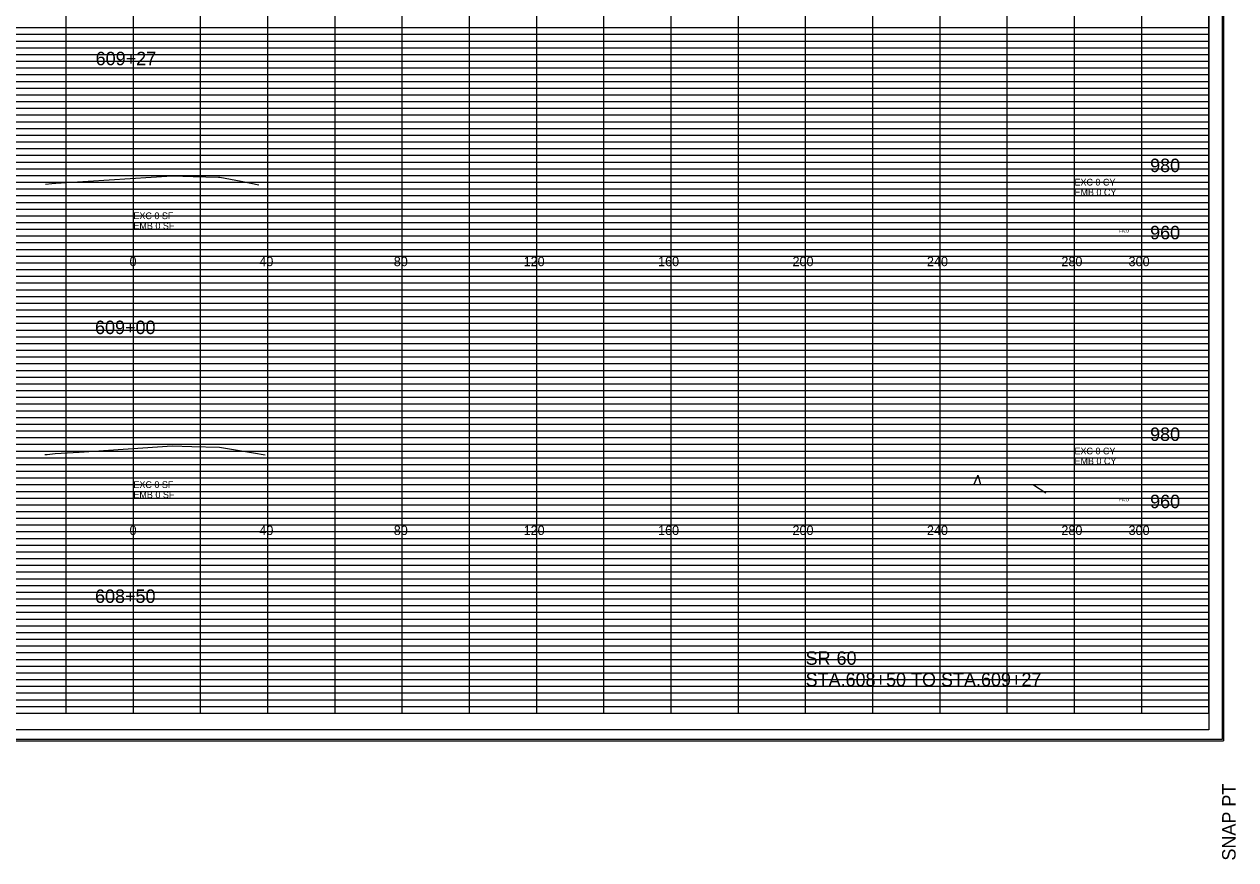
# Model space of a CAD drawing. Extents: x 2313580 to 2322968, y 282099 to 303247.
# Drawn here: x 2321916 to 2322276.5, y 287544 to 287792.7 of the extents above; entities that cross this region are included whole.
import ezdxf

# ---------------------------------------------------------------- set-up
doc = ezdxf.new("R2010")
doc.units = 0
for name, color, linetype in [('DESIGN - EARTHWORK - Excavation Limit Lines', 7, 'Continuous'), ('DESIGN - SHEET - Corner Text', 7, 'Continuous'), ('DESIGN - SHEET - Light Grid', 7, 'Continuous'), ('DESIGN - SHEET - Linework', 7, 'Continuous'), ('DESIGN - SHEET - Plot Shape', 7, 'Continuous'), ('DESIGN - TYPICAL - Text', 7, 'Continuous'), ('Prop_ CL text', 7, 'Continuous'), ('SURVEY - GROUND - Top of Ground', 7, 'Continuous')]:
    doc.layers.add(name, color=color, linetype=linetype)

msp = doc.modelspace()

# ---------------------------------------------------------------- linework, layer by layer
at = {"layer": 'DESIGN - SHEET - Light Grid'}
for p, q in [((2321788.48, 287791.67), (2321948.48, 287791.67)), ((2321788.48, 287789.67), (2321948.48, 287789.67)), ((2321948.48, 287791.67), (2322108.48, 287791.67)), ((2321948.48, 287789.67), (2322108.48, 287789.67)), ((2322108.48, 287791.67), (2322268.48, 287791.67)), ((2322108.48, 287789.67), (2322268.48, 287789.67)), ((2321788.48, 287785.67), (2321948.48, 287785.67)), ((2321948.48, 287785.67), (2322108.48, 287785.67)), ((2322108.48, 287785.67), (2322268.48, 287785.67)), ((2321788.48, 287783.67), (2321948.48, 287783.67)), ((2321788.48, 287781.67), (2321948.48, 287781.67)), ((2321948.48, 287783.67), (2322108.48, 287783.67)), ((2321948.48, 287781.67), (2322108.48, 287781.67)), ((2322108.48, 287783.67), (2322268.48, 287783.67)), ((2322108.48, 287781.67), (2322268.48, 287781.67)), ((2321788.48, 287779.67), (2321948.48, 287779.67)), ((2321788.48, 287777.67), (2321948.48, 287777.67)), ((2321948.48, 287779.67), (2322108.48, 287779.67)), ((2321948.48, 287777.67), (2322108.48, 287777.67)), ((2322108.48, 287779.67), (2322268.48, 287779.67)), ((2322108.48, 287777.67), (2322268.48, 287777.67)), ((2321788.48, 287775.67), (2321948.48, 287775.67)), ((2321948.48, 287775.67), (2322108.48, 287775.67)), ((2322108.48, 287775.67), (2322268.48, 287775.67)), ((2321788.48, 287773.67), (2321948.48, 287773.67)), ((2321788.48, 287771.67), (2321948.48, 287771.67)), ((2321948.48, 287773.67), (2322108.48, 287773.67)), ((2321948.48, 287771.67), (2322108.48, 287771.67)), ((2322108.48, 287773.67), (2322268.48, 287773.67)), ((2322108.48, 287771.67), (2322268.48, 287771.67)), ((2321788.48, 287769.67), (2321948.48, 287769.67)), ((2321948.48, 287769.67), (2322108.48, 287769.67)), ((2322108.48, 287769.67), (2322268.48, 287769.67)), ((2321788.48, 287765.67), (2321948.48, 287765.67)), ((2321788.48, 287763.67), (2321948.48, 287763.67)), ((2321948.48, 287765.67), (2322108.48, 287765.67)), ((2321948.48, 287763.67), (2322108.48, 287763.67)), ((2322108.48, 287765.67), (2322268.48, 287765.67)), ((2322108.48, 287763.67), (2322268.48, 287763.67)), ((2321788.48, 287761.67), (2321948.48, 287761.67)), ((2321788.48, 287759.67), (2321948.48, 287759.67)), ((2321948.48, 287761.67), (2322108.48, 287761.67)), ((2321948.48, 287759.67), (2322108.48, 287759.67)), ((2322108.48, 287761.67), (2322268.48, 287761.67)), ((2322108.48, 287759.67), (2322268.48, 287759.67)), ((2321788.48, 287757.67), (2321948.48, 287757.67)), ((2321948.48, 287757.67), (2322108.48, 287757.67)), ((2322108.48, 287757.67), (2322268.48, 287757.67)), ((2321788.48, 287755.67), (2321948.48, 287755.67)), ((2321788.48, 287753.67), (2321948.48, 287753.67)), ((2321948.48, 287755.67), (2322108.48, 287755.67)), ((2321948.48, 287753.67), (2322108.48, 287753.67)), ((2322108.48, 287755.67), (2322268.48, 287755.67)), ((2322108.48, 287753.67), (2322268.48, 287753.67)), ((2321788.48, 287751.67), (2321948.48, 287751.67)), ((2321788.48, 287749.67), (2321948.48, 287749.67)), ((2321948.48, 287751.67), (2322108.48, 287751.67)), ((2321948.48, 287749.67), (2322108.48, 287749.67)), ((2322108.48, 287751.67), (2322268.48, 287751.67)), ((2322108.48, 287749.67), (2322268.48, 287749.67)), ((2321788.48, 287745.67), (2321948.48, 287745.67)), ((2321948.48, 287745.67), (2322108.48, 287745.67)), ((2322108.48, 287745.67), (2322268.48, 287745.67)), ((2321788.48, 287743.67), (2321948.48, 287743.67)), ((2321788.48, 287741.67), (2321948.48, 287741.67)), ((2321948.48, 287743.67), (2322108.48, 287743.67)), ((2321948.48, 287741.67), (2322108.48, 287741.67)), ((2322108.48, 287743.67), (2322268.48, 287743.67)), ((2322108.48, 287741.67), (2322268.48, 287741.67)), ((2321788.48, 287739.67), (2321948.48, 287739.67)), ((2321948.48, 287739.67), (2322108.48, 287739.67)), ((2322108.48, 287739.67), (2322268.48, 287739.67)), ((2321788.48, 287737.67), (2321948.48, 287737.67)), ((2321788.48, 287735.67), (2321948.48, 287735.67)), ((2321948.48, 287737.67), (2322108.48, 287737.67)), ((2321948.48, 287735.67), (2322108.48, 287735.67)), ((2322108.48, 287737.67), (2322268.48, 287737.67)), ((2322108.48, 287735.67), (2322268.48, 287735.67)), ((2321788.48, 287733.67), (2321948.48, 287733.67)), ((2321788.48, 287731.67), (2321948.48, 287731.67)), ((2321948.48, 287733.67), (2322108.48, 287733.67)), ((2321948.48, 287731.67), (2322108.48, 287731.67)), ((2322108.48, 287733.67), (2322268.48, 287733.67)), ((2322108.48, 287731.67), (2322268.48, 287731.67)), ((2321788.48, 287729.67), (2321948.48, 287729.67)), ((2321948.48, 287729.67), (2322108.48, 287729.67)), ((2322108.48, 287729.67), (2322268.48, 287729.67)), ((2321788.48, 287725.67), (2321948.48, 287725.67)), ((2321788.48, 287723.67), (2321948.48, 287723.67)), ((2321948.48, 287725.67), (2322108.48, 287725.67)), ((2321948.48, 287723.67), (2322108.48, 287723.67)), ((2322108.48, 287725.67), (2322268.48, 287725.67)), ((2322108.48, 287723.67), (2322268.48, 287723.67)), ((2321788.48, 287721.67), (2321948.48, 287721.67)), ((2321948.48, 287721.67), (2322108.48, 287721.67)), ((2322108.48, 287721.67), (2322268.48, 287721.67)), ((2321788.48, 287719.67), (2321948.48, 287719.67)), ((2321788.48, 287717.67), (2321948.48, 287717.67)), ((2321948.48, 287719.67), (2322108.48, 287719.67)), ((2321948.48, 287717.67), (2322108.48, 287717.67)), ((2322108.48, 287719.67), (2322268.48, 287719.67)), ((2322108.48, 287717.67), (2322268.48, 287717.67)), ((2321788.48, 287715.67), (2321948.48, 287715.67)), ((2321788.48, 287713.67), (2321948.48, 287713.67)), ((2321948.48, 287715.67), (2322108.48, 287715.67)), ((2321948.48, 287713.67), (2322108.48, 287713.67)), ((2322108.48, 287715.67), (2322268.48, 287715.67)), ((2322108.48, 287713.67), (2322268.48, 287713.67)), ((2321788.48, 287711.67), (2321948.48, 287711.67)), ((2321788.48, 287709.67), (2321948.48, 287709.67)), ((2321948.48, 287711.67), (2322108.48, 287711.67)), ((2321948.48, 287709.67), (2322108.48, 287709.67)), ((2322108.48, 287711.67), (2322268.48, 287711.67)), ((2322108.48, 287709.67), (2322268.48, 287709.67)), ((2321788.48, 287705.67), (2321948.48, 287705.67)), ((2321948.48, 287705.67), (2322108.48, 287705.67)), ((2322108.48, 287705.67), (2322268.48, 287705.67)), ((2321788.48, 287703.67), (2321948.48, 287703.67)), ((2321788.48, 287701.67), (2321948.48, 287701.67)), ((2321948.48, 287703.67), (2322108.48, 287703.67)), ((2321948.48, 287701.67), (2322108.48, 287701.67)), ((2322108.48, 287703.67), (2322268.48, 287703.67)), ((2322108.48, 287701.67), (2322268.48, 287701.67)), ((2321788.48, 287699.67), (2321948.48, 287699.67)), ((2321948.48, 287699.67), (2322108.48, 287699.67)), ((2322108.48, 287699.67), (2322268.48, 287699.67)), ((2321788.48, 287697.67), (2321948.48, 287697.67)), ((2321788.48, 287695.67), (2321948.48, 287695.67)), ((2321948.48, 287697.67), (2322108.48, 287697.67)), ((2321948.48, 287695.67), (2322108.48, 287695.67)), ((2322108.48, 287697.67), (2322268.48, 287697.67)), ((2322108.48, 287695.67), (2322268.48, 287695.67)), ((2321788.48, 287693.67), (2321948.48, 287693.67)), ((2321788.48, 287691.67), (2321948.48, 287691.67)), ((2321948.48, 287693.67), (2322108.48, 287693.67)), ((2321948.48, 287691.67), (2322108.48, 287691.67)), ((2322108.48, 287693.67), (2322268.48, 287693.67)), ((2322108.48, 287691.67), (2322268.48, 287691.67)), ((2321788.48, 287689.67), (2321948.48, 287689.67)), ((2321948.48, 287689.67), (2322108.48, 287689.67)), ((2322108.48, 287689.67), (2322268.48, 287689.67)), ((2321788.48, 287685.67), (2321948.48, 287685.67)), ((2321788.48, 287683.67), (2321948.48, 287683.67)), ((2321948.48, 287685.67), (2322108.48, 287685.67)), ((2321948.48, 287683.67), (2322108.48, 287683.67)), ((2322108.48, 287685.67), (2322268.48, 287685.67)), ((2322108.48, 287683.67), (2322268.48, 287683.67)), ((2321788.48, 287681.67), (2321948.48, 287681.67)), ((2321948.48, 287681.67), (2322108.48, 287681.67)), ((2322108.48, 287681.67), (2322268.48, 287681.67)), ((2321788.48, 287679.67), (2321948.48, 287679.67)), ((2321788.48, 287677.67), (2321948.48, 287677.67)), ((2321948.48, 287679.67), (2322108.48, 287679.67)), ((2321948.48, 287677.67), (2322108.48, 287677.67)), ((2322108.48, 287679.67), (2322268.48, 287679.67)), ((2322108.48, 287677.67), (2322268.48, 287677.67)), ((2321788.48, 287675.67), (2321948.48, 287675.67)), ((2321788.48, 287673.67), (2321948.48, 287673.67)), ((2321948.48, 287675.67), (2322108.48, 287675.67)), ((2321948.48, 287673.67), (2322108.48, 287673.67)), ((2322108.48, 287675.67), (2322268.48, 287675.67)), ((2322108.48, 287673.67), (2322268.48, 287673.67)), ((2321788.48, 287671.67), (2321948.48, 287671.67)), ((2321788.48, 287669.67), (2321948.48, 287669.67)), ((2321948.48, 287671.67), (2322108.48, 287671.67)), ((2321948.48, 287669.67), (2322108.48, 287669.67)), ((2322108.48, 287671.67), (2322268.48, 287671.67)), ((2322108.48, 287669.67), (2322268.48, 287669.67)), ((2321788.48, 287665.67), (2321948.48, 287665.67)), ((2321948.48, 287665.67), (2322108.48, 287665.67)), ((2322108.48, 287665.67), (2322268.48, 287665.67)), ((2321788.48, 287663.67), (2321948.48, 287663.67)), ((2321948.48, 287663.67), (2322108.48, 287663.67)), ((2322108.48, 287663.67), (2322268.48, 287663.67)), ((2321788.48, 287661.67), (2321948.48, 287661.67)), ((2321788.48, 287659.67), (2321948.48, 287659.67)), ((2321948.48, 287661.67), (2322108.48, 287661.67)), ((2321948.48, 287659.67), (2322108.48, 287659.67)), ((2322108.48, 287661.67), (2322268.48, 287661.67)), ((2322108.48, 287659.67), (2322268.48, 287659.67)), ((2321788.48, 287657.67), (2321948.48, 287657.67)), ((2321788.48, 287655.67), (2321948.48, 287655.67)), ((2321948.48, 287657.67), (2322108.48, 287657.67)), ((2321948.48, 287655.67), (2322108.48, 287655.67)), ((2322108.48, 287657.67), (2322268.48, 287657.67)), ((2322108.48, 287655.67), (2322268.48, 287655.67)), ((2321788.48, 287653.67), (2321948.48, 287653.67)), ((2321788.48, 287651.67), (2321948.48, 287651.67)), ((2321948.48, 287653.67), (2322108.48, 287653.67)), ((2321948.48, 287651.67), (2322108.48, 287651.67)), ((2322108.48, 287653.67), (2322268.48, 287653.67)), ((2322108.48, 287651.67), (2322268.48, 287651.67)), ((2321788.48, 287649.67), (2321948.48, 287649.67)), ((2321948.48, 287649.67), (2322108.48, 287649.67)), ((2322108.48, 287649.67), (2322268.48, 287649.67)), ((2321788.48, 287645.67), (2321948.48, 287645.67)), ((2321948.48, 287645.67), (2322108.48, 287645.67)), ((2322108.48, 287645.67), (2322268.48, 287645.67)), ((2321788.48, 287643.67), (2321948.48, 287643.67)), ((2321788.48, 287641.67), (2321948.48, 287641.67)), ((2321948.48, 287643.67), (2322108.48, 287643.67)), ((2321948.48, 287641.67), (2322108.48, 287641.67)), ((2322108.48, 287643.67), (2322268.48, 287643.67)), ((2322108.48, 287641.67), (2322268.48, 287641.67)), ((2321788.48, 287639.67), (2321948.48, 287639.67)), ((2321788.48, 287637.67), (2321948.48, 287637.67)), ((2321948.48, 287639.67), (2322108.48, 287639.67)), ((2321948.48, 287637.67), (2322108.48, 287637.67)), ((2322108.48, 287639.67), (2322268.48, 287639.67)), ((2322108.48, 287637.67), (2322268.48, 287637.67)), ((2321788.48, 287635.67), (2321948.48, 287635.67)), ((2321788.48, 287633.67), (2321948.48, 287633.67)), ((2321948.48, 287635.67), (2322108.48, 287635.67)), ((2321948.48, 287633.67), (2322108.48, 287633.67)), ((2322108.48, 287635.67), (2322268.48, 287635.67)), ((2322108.48, 287633.67), (2322268.48, 287633.67)), ((2321788.48, 287631.67), (2321948.48, 287631.67)), ((2321788.48, 287629.67), (2321948.48, 287629.67)), ((2321948.48, 287631.67), (2322108.48, 287631.67)), ((2321948.48, 287629.67), (2322108.48, 287629.67)), ((2322108.48, 287631.67), (2322268.48, 287631.67)), ((2322108.48, 287629.67), (2322268.48, 287629.67)), ((2321788.48, 287625.67), (2321948.48, 287625.67)), ((2321788.48, 287623.67), (2321948.48, 287623.67)), ((2321948.48, 287625.67), (2322108.48, 287625.67)), ((2321948.48, 287623.67), (2322108.48, 287623.67)), ((2322108.48, 287625.67), (2322268.48, 287625.67)), ((2322108.48, 287623.67), (2322268.48, 287623.67)), ((2321788.48, 287621.67), (2321948.48, 287621.67)), ((2321788.48, 287619.67), (2321948.48, 287619.67)), ((2321948.48, 287621.67), (2322108.48, 287621.67)), ((2321948.48, 287619.67), (2322108.48, 287619.67)), ((2322108.48, 287621.67), (2322268.48, 287621.67)), ((2322108.48, 287619.67), (2322268.48, 287619.67)), ((2321788.48, 287617.67), (2321948.48, 287617.67)), ((2321788.48, 287615.67), (2321948.48, 287615.67)), ((2321948.48, 287617.67), (2322108.48, 287617.67)), ((2321948.48, 287615.67), (2322108.48, 287615.67)), ((2322108.48, 287617.67), (2322268.48, 287617.67)), ((2322108.48, 287615.67), (2322268.48, 287615.67)), ((2321788.48, 287613.67), (2321948.48, 287613.67)), ((2321788.48, 287611.67), (2321948.48, 287611.67)), ((2321948.48, 287613.67), (2322108.48, 287613.67)), ((2321948.48, 287611.67), (2322108.48, 287611.67)), ((2322108.48, 287613.67), (2322268.48, 287613.67)), ((2322108.48, 287611.67), (2322268.48, 287611.67)), ((2321788.48, 287609.67), (2321948.48, 287609.67)), ((2321948.48, 287609.67), (2322108.48, 287609.67)), ((2322108.48, 287609.67), (2322268.48, 287609.67)), ((2321788.48, 287605.67), (2321948.48, 287605.67)), ((2321948.48, 287605.67), (2322108.48, 287605.67)), ((2322108.48, 287605.67), (2322268.48, 287605.67)), ((2321788.48, 287603.67), (2321948.48, 287603.67)), ((2321788.48, 287601.67), (2321948.48, 287601.67)), ((2321948.48, 287603.67), (2322108.48, 287603.67)), ((2321948.48, 287601.67), (2322108.48, 287601.67)), ((2322108.48, 287603.67), (2322268.48, 287603.67)), ((2322108.48, 287601.67), (2322268.48, 287601.67)), ((2321788.48, 287599.67), (2321948.48, 287599.67)), ((2321788.48, 287597.67), (2321948.48, 287597.67)), ((2321948.48, 287599.67), (2322108.48, 287599.67)), ((2321948.48, 287597.67), (2322108.48, 287597.67)), ((2322108.48, 287599.67), (2322268.48, 287599.67)), ((2322108.48, 287597.67), (2322268.48, 287597.67)), ((2321788.48, 287595.67), (2321948.48, 287595.67)), ((2321788.48, 287593.67), (2321948.48, 287593.67)), ((2321948.48, 287595.67), (2322108.48, 287595.67)), ((2321948.48, 287593.67), (2322108.48, 287593.67)), ((2322108.48, 287595.67), (2322268.48, 287595.67)), ((2322108.48, 287593.67), (2322268.48, 287593.67)), ((2321788.48, 287591.67), (2321948.48, 287591.67)), ((2321948.48, 287591.67), (2322108.48, 287591.67)), ((2322108.48, 287591.67), (2322268.48, 287591.67)), ((2321788.48, 287589.67), (2321948.48, 287589.67)), ((2321948.48, 287589.67), (2322108.48, 287589.67)), ((2322108.48, 287589.67), (2322268.48, 287589.67))]:
    msp.add_line(p, q, dxfattribs=at)
at = {"layer": 'DESIGN - SHEET - Linework'}
for p, q in [((2322272.82, 288015.95), (2322272.82, 287579.39)), ((2321928.48, 287587.67), (2321928.48, 288007.67)), ((2321948.48, 287587.67), (2321948.48, 288007.67)), ((2321968.48, 287587.67), (2321968.48, 288007.67)), ((2321988.48, 287587.67), (2321988.48, 288007.67)), ((2322008.48, 287587.67), (2322008.48, 288007.67)), ((2322028.48, 287587.67), (2322028.48, 288007.67)), ((2322048.48, 287587.67), (2322048.48, 288007.67)), ((2322068.48, 287587.67), (2322068.48, 288007.67)), ((2322088.48, 287587.67), (2322088.48, 288007.67)), ((2322108.48, 287587.67), (2322108.48, 288007.67)), ((2322128.48, 287587.67), (2322128.48, 288007.67)), ((2322148.48, 287587.67), (2322148.48, 288007.67)), ((2322168.48, 287587.67), (2322168.48, 288007.67)), ((2322188.48, 287587.67), (2322188.48, 287987.67)), ((2322208.48, 287587.67), (2322208.48, 287987.67)), ((2322228.48, 287587.67), (2322228.48, 287987.67)), ((2322248.48, 287587.67), (2322248.48, 287987.67)), ((2321628.48, 287787.67), (2322268.48, 287787.67)), ((2321628.48, 287767.67), (2322268.48, 287767.67)), ((2321628.48, 287747.67), (2322268.48, 287747.67)), ((2321628.48, 287727.67), (2322268.48, 287727.67)), ((2321628.48, 287707.67), (2322268.48, 287707.67)), ((2321628.48, 287687.67), (2322268.48, 287687.67)), ((2321628.48, 287667.67), (2322268.48, 287667.67)), ((2321628.48, 287647.67), (2322268.48, 287647.67)), ((2321628.48, 287627.67), (2322268.48, 287627.67)), ((2321628.48, 287607.67), (2322268.48, 287607.67)), ((2321592.02, 287579.39), (2322272.82, 287579.39))]:
    msp.add_line(p, q, dxfattribs=at)
msp.add_lwpolyline([(2321628.48, 288007.67), (2321628.48, 287587.67), (2322268.48, 287587.67), (2322268.48, 288007.67), (2321628.48, 288007.67)], dxfattribs=at)
at = {"layer": 'DESIGN - SHEET - Plot Shape'}
for points in [[(2321592.42, 288015.55), (2322272.42, 288015.55), (2322272.42, 287579.79), (2321592.42, 287579.79)], [(2321611.48, 288007.67), (2322268.48, 288007.67), (2322268.48, 287582.67), (2321611.48, 287582.67)]]:
    msp.add_lwpolyline(points, close=True, dxfattribs=at)
at = {"layer": 'SURVEY - GROUND - Top of Ground'}
for points in [[(2321922.36, 287745.08), (2321924.25, 287745.24), (2321925.38, 287745.34), (2321935.03, 287745.97), (2321960.04, 287747.51), (2321966.23, 287747.34), (2321973.76, 287747.19), (2321974.2, 287747.15), (2321980.53, 287746), (2321985.76, 287744.9)], [(2321922.13, 287664.64), (2321922.37, 287664.65), (2321922.84, 287664.68), (2321925.2, 287664.9), (2321932.36, 287665.36), (2321960.01, 287667.17), (2321965.9, 287667.06), (2321974.1, 287666.83), (2321984.23, 287665.15), (2321987.65, 287664.54)], [(2322198.58, 287655.62), (2322199.59, 287658.12), (2322199.72, 287658.47), (2322199.82, 287658.14), (2322200.52, 287655.71), (2322216.26, 287655.62), (2322220.01, 287653.19)]]:
    msp.add_lwpolyline(points, dxfattribs=at)

# ---------------------------------------------------------------- texts
at = {"layer": 'DESIGN - EARTHWORK - Excavation Limit Lines'}
for s, p in [('EXC 0 CY', (2322228.48, 287744.67)), ('EMB 0 CY', (2322228.48, 287741.67)), ('EXC 0 SF', (2321948.48, 287734.67)), ('EMB 0 SF', (2321948.48, 287731.67)), ('EXC 0 CY', (2322228.48, 287664.67)), ('EMB 0 CY', (2322228.48, 287661.67)), ('EXC 0 SF', (2321948.48, 287654.67)), ('EMB 0 SF', (2321948.48, 287651.67))]:
    msp.add_text(s, height=2, dxfattribs=at).set_placement(p)
at = {"layer": 'DESIGN - SHEET - Corner Text'}
msp.add_text('SNAP PT  ', height=4, rotation=90, dxfattribs=at).set_placement((2322276.42, 287543.79))
at = {"layer": 'DESIGN - TYPICAL - Text'}
for s, height, p in [('609+27', 4, (2321937.24, 287780.47)), ('980', 4, (2322250.98, 287748.67)), ('960', 4, (2322250.98, 287728.67)), ('0', 2.8, (2321947.32, 287720.67)), ('40', 2.8, (2321985.95, 287720.67)), ('80', 2.8, (2322025.95, 287720.67)), ('120', 2.8, (2322064.59, 287720.67)), ('160', 2.8, (2322104.59, 287720.67)), ('200', 2.8, (2322144.59, 287720.67)), ('240', 2.8, (2322184.59, 287720.67)), ('280', 2.8, (2322224.59, 287720.67)), ('300', 2.8, (2322244.59, 287720.67)), ('609+00', 4, (2321937.06, 287700.47)), ('980', 4, (2322250.98, 287668.67)), ('960', 4, (2322250.98, 287648.67)), ('0', 2.8, (2321947.32, 287640.67)), ('40', 2.8, (2321985.95, 287640.67)), ('80', 2.8, (2322025.95, 287640.67)), ('120', 2.8, (2322064.59, 287640.67)), ('160', 2.8, (2322104.59, 287640.67)), ('200', 2.8, (2322144.59, 287640.67)), ('240', 2.8, (2322184.59, 287640.67)), ('280', 2.8, (2322224.59, 287640.67)), ('300', 2.8, (2322244.59, 287640.67)), ('608+50', 4, (2321937.06, 287620.47)), ('SR-60', 4, (2322148.48, 287602.05)), ('STA.608+50 TO STA.609+27', 4, (2322148.48, 287595.67))]:
    msp.add_text(s, height=height, dxfattribs=at).set_placement(p)
at = {"layer": 'Prop_ CL text'}
for p in [(2322241.72, 287730.67), (2322241.72, 287650.67)]:
    msp.add_text('FA:0', height=1, dxfattribs=at).set_placement(p)

doc.saveas('drawing.dxf')
